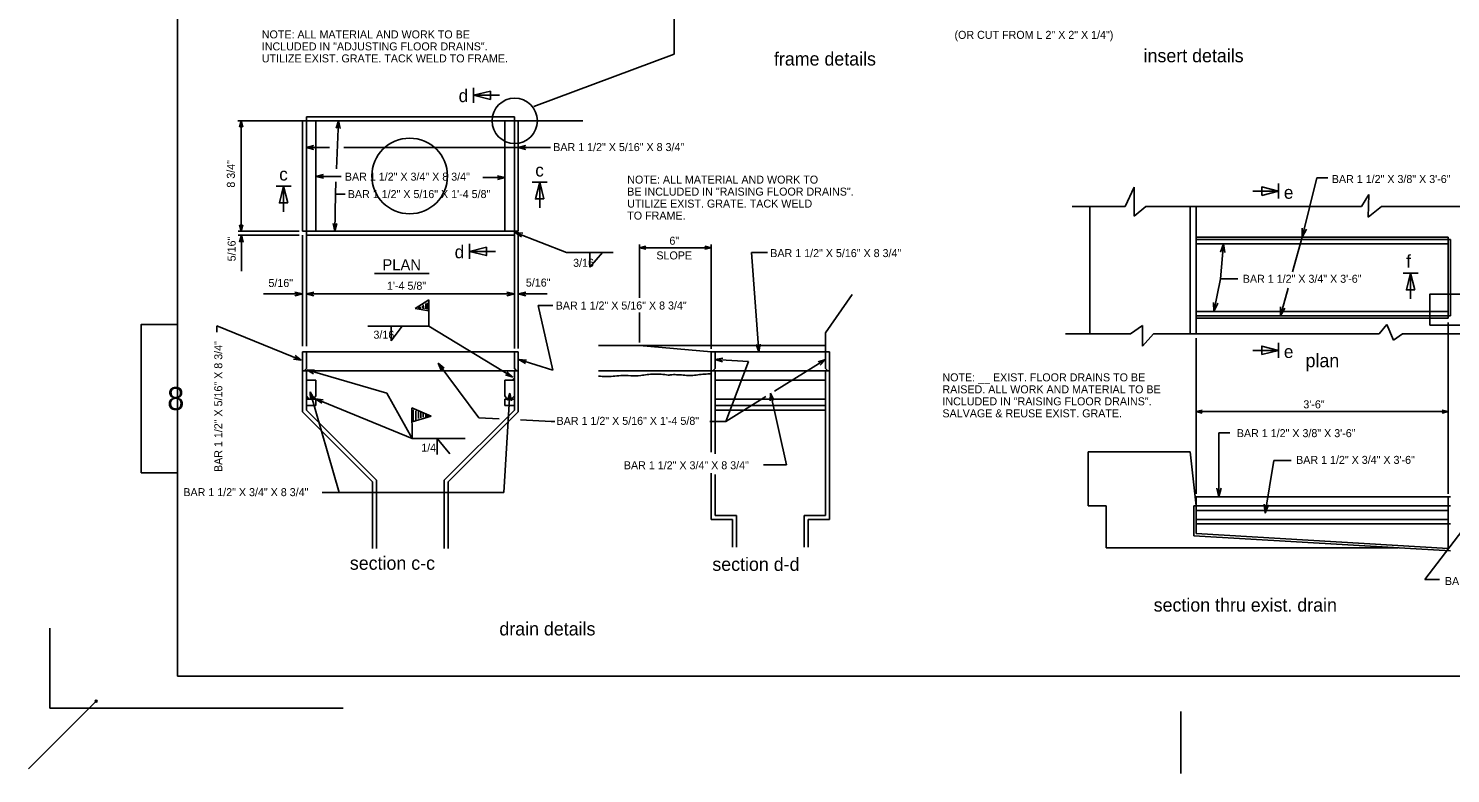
# Model space of a CAD drawing. Extents: x 973.2 to 1069.7, y 1484.4 to 1549.5.
# Drawn here: x 975.6 to 1034.8, y 1484.4 to 1515.4 of the extents above; entities that cross this region are included whole.
import ezdxf

# ---------------------------------------------------------------- set-up
doc = ezdxf.new("R2010")
doc.units = 0
for name, color, linetype in [('Level 1', 7, 'Continuous'), ('Level 2', 7, 'Continuous'), ('Level 37', 7, 'Continuous'), ('Level 49', 7, 'Continuous')]:
    doc.layers.add(name, color=color, linetype=linetype)

msp = doc.modelspace()

# ---------------------------------------------------------------- linework, layer by layer
at = {"layer": 'Level 1'}
for p, q in [((981.8, 1488.431), (981.8, 1544.364)), ((976.473, 1490.436), (976.473, 1487.1)), ((981.8, 1488.431), (1065.368, 1488.431)), ((976.473, 1487.1), (988.692, 1487.1))]:
    msp.add_line(p, q, dxfattribs=at)
msp.add_lwpolyline([(981.799, 1503.093), (980.288, 1503.093), (980.288, 1496.91), (981.799, 1496.91)], close=True, dxfattribs=at)
at = {"layer": 'Level 2'}
for p, q in [((1002.483, 1514.351), (1002.483, 1538.904)), ((996.637, 1512.173), (1002.483, 1514.351)), ((994.121, 1512.954), (994.121, 1512.33)), ((994.121, 1512.642), (995.2, 1512.642)), ((986.999, 1511.575), (984.308, 1511.575)), ((984.448, 1506.982), (984.448, 1511.575)), ((986.999, 1511.575), (995.989, 1511.575)), ((986.999, 1506.982), (986.999, 1511.575)), ((987.163, 1511.739), (995.825, 1511.739)), ((987.163, 1506.818), (987.163, 1511.739)), ((987.557, 1506.982), (987.557, 1511.575)), ((988.497, 1511.575), (988.406, 1511.264)), ((988.417, 1509.579), (988.497, 1511.575)), ((988.497, 1511.575), (988.564, 1511.257)), ((995.432, 1506.982), (995.432, 1511.575)), ((995.825, 1506.818), (995.825, 1511.739)), ((995.989, 1506.982), (995.989, 1511.575)), ((995.989, 1511.575), (998.674, 1511.575)), ((987.163, 1510.464), (987.478, 1510.543)), ((987.163, 1510.464), (987.478, 1510.386)), ((988.129, 1510.464), (987.163, 1510.464)), ((995.989, 1510.464), (988.718, 1510.464)), ((995.989, 1510.464), (996.304, 1510.543)), ((997.335, 1510.464), (995.989, 1510.464)), ((995.989, 1510.464), (996.304, 1510.386)), ((987.557, 1509.262), (987.872, 1509.34)), ((988.615, 1509.262), (987.557, 1509.262)), ((987.557, 1509.262), (987.872, 1509.183)), ((994.518, 1509.212), (995.433, 1509.212)), ((995.433, 1509.212), (995.118, 1509.291)), ((995.433, 1509.212), (995.118, 1509.134)), ((986.528, 1508.86), (985.904, 1508.86)), ((986.216, 1508.86), (986.216, 1507.782)), ((988.375, 1508.525), (988.396, 1509.04)), ((997.193, 1509.027), (996.569, 1509.027)), ((996.881, 1509.027), (996.881, 1507.949)), ((1021.261, 1508.01), (1021.637, 1508.81)), ((1021.637, 1508.81), (1021.637, 1507.607)), ((1027.658, 1508.646), (1026.579, 1508.646)), ((1027.658, 1508.334), (1027.658, 1508.958)), ((1029.25, 1509.194), (1028.642, 1506.729)), ((1029.707, 1509.194), (1029.25, 1509.194)), ((988.375, 1508.525), (988.35, 1506.982)), ((988.781, 1508.525), (988.375, 1508.525)), ((1031.414, 1508.509), (1031.115, 1508.01)), ((1031.414, 1508.509), (1031.389, 1507.556)), ((1019.055, 1508.01), (1021.261, 1508.01)), ((1019.799, 1502.7), (1019.799, 1508.01)), ((1021.637, 1507.607), (1022.121, 1508.01)), ((1022.121, 1508.01), (1031.115, 1508.01)), ((1023.974, 1502.7), (1023.974, 1508.01)), ((1024.223, 1502.7), (1024.223, 1508.01)), ((1031.389, 1507.556), (1031.941, 1508.01)), ((1031.941, 1508.01), (1036.804, 1508.01)), ((986.868, 1506.982), (984.317, 1506.982)), ((986.999, 1506.982), (995.989, 1506.982)), ((988.35, 1506.982), (988.276, 1507.298)), ((988.35, 1506.982), (988.434, 1507.295)), ((997.998, 1506.091), (995.862, 1506.929)), ((995.862, 1506.929), (996.184, 1506.888)), ((995.862, 1506.929), (996.127, 1506.741)), ((1028.642, 1506.729), (1028.641, 1507.1)), ((1028.642, 1506.729), (1028.815, 1507.057)), ((986.868, 1506.818), (984.317, 1506.818)), ((984.454, 1506.832), (984.376, 1506.517)), ((984.454, 1506.832), (984.454, 1505.311)), ((984.454, 1506.832), (984.533, 1506.517)), ((986.999, 1506.818), (986.999, 1502.179)), ((987.163, 1506.818), (995.825, 1506.818)), ((987.163, 1506.818), (987.163, 1502.179)), ((993.957, 1506.444), (993.957, 1505.82)), ((995.825, 1506.818), (995.825, 1502.089)), ((995.989, 1506.818), (995.989, 1502.089)), ((1001.038, 1504.204), (1001.038, 1506.419)), ((1001.038, 1506.288), (1004.024, 1506.288)), ((1004.024, 1502.08), (1004.024, 1506.419)), ((1024.223, 1506.729), (1034.724, 1506.729)), ((1024.223, 1506.635), (1024.223, 1506.729)), ((1024.223, 1506.635), (1034.818, 1506.635)), ((1024.223, 1506.448), (1024.223, 1506.635)), ((1024.223, 1506.448), (1034.724, 1506.448)), ((1025.233, 1504.995), (1025.355, 1506.448)), ((1025.355, 1506.448), (1025.235, 1506.097)), ((1025.355, 1506.448), (1025.415, 1506.082)), ((1028.642, 1506.729), (1028.238, 1505.279)), ((1034.724, 1503.354), (1034.724, 1506.729)), ((1034.818, 1503.448), (1034.818, 1506.635)), ((993.957, 1506.132), (995.036, 1506.132)), ((997.998, 1506.091), (999.937, 1506.091)), ((998.973, 1506.091), (998.973, 1505.475)), ((998.973, 1505.475), (999.496, 1506.091)), ((1006.371, 1506.088), (1005.708, 1506.088)), ((1005.708, 1506.088), (1006.005, 1501.949)), ((989.995, 1505.211), (992.279, 1505.211)), ((1033.466, 1505.231), (1032.842, 1505.231)), ((1033.154, 1505.231), (1033.154, 1504.152)), ((1024.959, 1503.635), (1025.233, 1504.995)), ((1025.964, 1504.995), (1025.233, 1504.995)), ((1028.051, 1504.607), (1027.729, 1503.448)), ((986.999, 1504.36), (985.376, 1504.36)), ((986.999, 1504.36), (986.684, 1504.438)), ((986.999, 1504.36), (986.684, 1504.281)), ((987.163, 1504.36), (987.478, 1504.438)), ((987.163, 1504.36), (995.825, 1504.36)), ((987.163, 1504.36), (987.478, 1504.281)), ((992.258, 1504.11), (991.691, 1503.76)), ((992.06, 1503.741), (992.032, 1503.902)), ((992.136, 1503.741), (992.136, 1503.968)), ((992.202, 1503.713), (992.202, 1503.987)), ((992.258, 1503.023), (992.258, 1504.11)), ((995.825, 1504.36), (995.51, 1504.438)), ((995.825, 1504.36), (995.51, 1504.281)), ((995.989, 1504.36), (996.304, 1504.438)), ((995.989, 1504.36), (997.197, 1504.36)), ((995.989, 1504.36), (996.304, 1504.281)), ((997.434, 1503.885), (996.82, 1503.885)), ((996.82, 1503.885), (997.434, 1501.184)), ((1008.782, 1502.736), (1009.9, 1504.334)), ((1024.959, 1503.635), (1024.942, 1504.006)), ((1024.959, 1503.635), (1025.119, 1503.971)), ((991.691, 1503.76), (992.258, 1503.656)), ((991.862, 1503.76), (991.833, 1503.817)), ((991.909, 1503.76), (991.909, 1503.826)), ((991.994, 1503.76), (991.994, 1503.855)), ((1001.038, 1502.342), (1001.038, 1503.591)), ((1024.223, 1503.635), (1034.724, 1503.635)), ((1024.223, 1503.635), (1024.223, 1503.448)), ((1024.223, 1503.448), (1034.818, 1503.448)), ((1024.223, 1503.354), (1024.223, 1503.448)), ((1024.223, 1503.354), (1034.724, 1503.354)), ((1027.729, 1503.448), (1027.739, 1503.819)), ((1027.729, 1503.448), (1027.912, 1503.771)), ((983.44, 1502.774), (983.44, 1503.027)), ((983.44, 1503.027), (986.951, 1501.602)), ((992.258, 1503.023), (989.725, 1503.023)), ((990.689, 1503.023), (990.689, 1502.406)), ((990.689, 1502.406), (991.153, 1503.023)), ((992.258, 1503.023), (995.76, 1500.89)), ((1008.782, 1502.211), (1008.782, 1502.736)), ((1018.779, 1502.7), (1021.487, 1502.7)), ((1021.487, 1502.7), (1021.988, 1503.044)), ((1021.988, 1503.044), (1021.988, 1502.191)), ((1021.988, 1502.191), (1022.449, 1502.7)), ((1022.449, 1502.7), (1031.841, 1502.7)), ((1031.841, 1502.7), (1032.167, 1503.094)), ((1032.167, 1503.094), (1032.442, 1502.442)), ((1032.442, 1502.442), (1032.818, 1502.7)), ((1032.818, 1502.7), (1036.83, 1502.7)), ((1034.724, 1499.584), (1034.724, 1503.169)), ((999.334, 1502.211), (1008.782, 1502.211)), ((1001.038, 1502.211), (1004.024, 1501.949)), ((1006.005, 1501.949), (1005.903, 1502.257)), ((1006.005, 1501.949), (1006.06, 1502.268)), ((1008.782, 1501.949), (1008.782, 1502.211)), ((1024.224, 1499.584), (1024.224, 1502.517)), ((1027.658, 1501.698), (1027.658, 1502.322)), ((986.951, 1501.602), (986.629, 1501.647)), ((986.951, 1501.602), (986.689, 1501.793)), ((986.999, 1501.161), (986.999, 1501.948)), ((986.999, 1501.948), (987.163, 1501.948)), ((987.163, 1501.948), (995.825, 1501.948)), ((987.163, 1501.948), (987.163, 1501.255)), ((995.989, 1501.948), (995.825, 1501.948)), ((995.825, 1501.948), (995.825, 1501.255)), ((995.989, 1501.161), (995.989, 1501.948)), ((997.434, 1501.184), (996.01, 1501.627)), ((996.01, 1501.627), (996.334, 1501.608)), ((996.01, 1501.627), (996.287, 1501.458)), ((1004.024, 1501.161), (1004.024, 1501.949)), ((1004.024, 1501.949), (1004.187, 1501.949)), ((1004.188, 1501.949), (1008.781, 1501.949)), ((1004.188, 1501.949), (1004.188, 1501.255)), ((1004.188, 1501.627), (1004.506, 1501.688)), ((1005.584, 1501.553), (1004.188, 1501.627)), ((1004.188, 1501.627), (1004.498, 1501.531)), ((1004.635, 1499.049), (1005.584, 1501.553)), ((1006.655, 1500.304), (1008.781, 1501.627)), ((1008.781, 1501.627), (1008.473, 1501.527)), ((1008.781, 1501.627), (1008.556, 1501.393)), ((1008.781, 1501.949), (1008.781, 1501.255)), ((1008.945, 1501.949), (1008.782, 1501.949)), ((1008.945, 1501.161), (1008.945, 1501.949)), ((1027.658, 1502.01), (1026.579, 1502.01)), ((986.999, 1501.161), (995.989, 1501.161)), ((986.999, 1501.161), (986.999, 1499.455)), ((987.069, 1501.161), (986.999, 1501.161)), ((987.163, 1501.255), (987.069, 1501.161)), ((987.087, 1501.161), (987.163, 1501.161)), ((987.163, 1501.161), (987.163, 1499.523)), ((990.508, 1500.225), (987.178, 1501.195)), ((987.178, 1501.195), (987.502, 1501.182)), ((987.178, 1501.195), (987.458, 1501.031)), ((992.646, 1501.479), (994.34, 1499.196)), ((992.646, 1501.479), (992.897, 1501.273)), ((992.646, 1501.479), (992.771, 1501.18)), ((995.76, 1500.89), (995.45, 1500.987)), ((995.76, 1500.89), (995.532, 1501.121)), ((995.825, 1501.255), (995.919, 1501.161)), ((995.825, 1501.161), (995.825, 1499.523)), ((995.919, 1501.161), (995.989, 1501.161)), ((995.989, 1501.161), (995.989, 1499.455)), ((999.334, 1501.161), (1008.946, 1501.161)), ((1004.093, 1501.161), (1004.024, 1501.161)), ((1004.024, 1501.161), (1004.024, 1497.772)), ((1004.188, 1501.255), (1004.093, 1501.161)), ((1004.188, 1501.161), (1008.781, 1501.161)), ((1004.188, 1501.161), (1004.188, 1497.698)), ((1008.781, 1501.255), (1008.876, 1501.161)), ((1008.782, 1501.161), (1008.782, 1495.124)), ((1008.876, 1501.161), (1008.945, 1501.161)), ((1008.946, 1501.161), (1008.946, 1494.96)), ((987.557, 1500.768), (987.163, 1500.768)), ((987.163, 1500.768), (987.163, 1500.103)), ((987.557, 1500.113), (987.557, 1500.768)), ((995.432, 1500.112), (995.432, 1500.768)), ((995.432, 1500.768), (995.825, 1500.768)), ((995.732, 1500.768), (995.826, 1500.862)), ((995.826, 1500.768), (995.826, 1500.112)), ((1004.188, 1500.768), (1008.782, 1500.768)), ((1004.188, 1499.98), (1004.188, 1500.768)), ((1008.782, 1499.98), (1008.782, 1500.768)), ((987.163, 1500.103), (987.27, 1499.98)), ((987.163, 1499.98), (987.557, 1499.98)), ((987.27, 1499.98), (987.463, 1499.98)), ((988.53, 1496.085), (987.319, 1500.276)), ((987.319, 1500.276), (987.482, 1499.995)), ((987.319, 1500.276), (987.331, 1499.952)), ((987.463, 1499.98), (987.557, 1500.113)), ((991.57, 1498.336), (987.539, 1499.996)), ((987.539, 1499.996), (987.86, 1499.949)), ((987.539, 1499.996), (987.8, 1499.804)), ((987.557, 1499.98), (987.557, 1499.718)), ((991.57, 1498.336), (990.508, 1500.225)), ((995.393, 1496.085), (995.642, 1500.227)), ((995.432, 1500.112), (995.527, 1499.98)), ((995.432, 1499.98), (995.432, 1499.718)), ((995.432, 1499.98), (995.825, 1499.98)), ((995.695, 1499.98), (995.527, 1499.98)), ((995.642, 1500.227), (995.544, 1499.917)), ((995.642, 1500.227), (995.701, 1499.908)), ((995.695, 1499.98), (995.826, 1500.112)), ((1004.188, 1499.98), (1008.782, 1499.98)), ((1004.635, 1499.049), (1006.304, 1500.086)), ((1006.493, 1500.225), (1006.484, 1499.901)), ((1007.153, 1497.245), (1006.493, 1500.225)), ((1006.493, 1500.225), (1006.638, 1499.934)), ((986.999, 1499.455), (989.92, 1496.535)), ((987.163, 1499.718), (987.557, 1499.718)), ((987.163, 1499.523), (990.083, 1496.602)), ((991.56, 1499.613), (991.57, 1498.336)), ((991.56, 1499.613), (992.364, 1499.272)), ((992.364, 1499.272), (991.564, 1499.036)), ((991.612, 1499.074), (991.612, 1499.532)), ((991.726, 1499.121), (991.726, 1499.485)), ((991.839, 1499.173), (991.839, 1499.461)), ((991.924, 1499.192), (991.924, 1499.419)), ((992.028, 1499.22), (992.028, 1499.376)), ((992.141, 1499.234), (992.141, 1499.358)), ((992.212, 1499.258), (992.212, 1499.301)), ((995.825, 1499.523), (992.906, 1496.603)), ((995.989, 1499.455), (993.069, 1496.535)), ((994.34, 1499.196), (995.199, 1499.154)), ((995.432, 1499.718), (995.825, 1499.718)), ((1004.188, 1499.718), (1008.782, 1499.718)), ((1004.188, 1499.523), (1008.782, 1499.523)), ((1024.224, 1496.029), (1024.224, 1499.584)), ((1024.224, 1499.459), (1034.724, 1499.459)), ((1034.224, 1499.459), (1034.724, 1499.459)), ((1034.724, 1496.029), (1034.724, 1499.584)), ((1034.724, 1496.751), (1034.724, 1499.584)), ((996.08, 1499.111), (997.36, 1499.049)), ((997.36, 1499.049), (997.513, 1499.049)), ((1003.965, 1499.049), (1004.635, 1499.049)), ((1025.629, 1498.573), (1025.169, 1498.573)), ((1025.169, 1498.573), (1025.172, 1495.904)), ((991.57, 1498.336), (993.772, 1498.336)), ((992.609, 1498.336), (992.609, 1497.675)), ((992.609, 1498.336), (993.134, 1497.703)), ((1023.974, 1497.779), (1019.724, 1497.779)), ((1019.724, 1497.779), (1019.724, 1495.529)), ((1024.224, 1495.529), (1023.974, 1497.779)), ((1027.455, 1497.417), (1027.09, 1495.225)), ((1028.185, 1497.417), (1027.455, 1497.417)), ((1004.024, 1496.888), (1004.024, 1494.96)), ((1004.188, 1496.839), (1004.188, 1495.124)), ((1006.2, 1497.245), (1007.153, 1497.245)), ((989.92, 1496.535), (989.92, 1493.747)), ((990.083, 1496.602), (990.083, 1493.747)), ((992.906, 1496.603), (992.906, 1493.747)), ((993.069, 1496.535), (993.069, 1493.747)), ((1025.172, 1495.904), (1025.082, 1496.264)), ((1025.172, 1495.904), (1025.262, 1496.264)), ((987.825, 1496.085), (995.393, 1496.085)), ((1024.224, 1495.904), (1034.818, 1495.904)), ((1024.224, 1495.529), (1024.224, 1495.904)), ((1027.09, 1495.225), (1027.06, 1495.595)), ((1034.724, 1495.529), (1034.724, 1495.904)), ((1004.188, 1495.124), (1005.074, 1495.124)), ((1005.074, 1495.124), (1005.074, 1493.811)), ((1007.896, 1495.124), (1007.896, 1493.811)), ((1007.896, 1495.124), (1008.782, 1495.124)), ((1019.724, 1495.529), (1020.474, 1495.529)), ((1020.474, 1495.529), (1020.474, 1493.779)), ((1024.13, 1495.529), (1024.13, 1494.284)), ((1024.13, 1495.529), (1024.223, 1495.529)), ((1024.224, 1495.529), (1024.224, 1494.373)), ((1024.224, 1495.529), (1034.818, 1495.529)), ((1024.224, 1495.341), (1034.724, 1495.341)), ((1024.224, 1494.966), (1024.224, 1495.341)), ((1027.09, 1495.225), (1027.238, 1495.566)), ((1034.724, 1495.529), (1034.724, 1493.754)), ((1034.724, 1494.966), (1034.724, 1495.341)), ((1004.024, 1494.96), (1004.91, 1494.96)), ((1004.91, 1494.96), (1004.91, 1493.811)), ((1008.06, 1494.96), (1008.06, 1493.811)), ((1008.06, 1494.96), (1008.946, 1494.96)), ((1024.224, 1494.966), (1034.724, 1494.966)), ((1024.224, 1494.779), (1034.818, 1494.779)), ((1033.748, 1492.456), (1035.642, 1494.951)), ((1024.13, 1494.284), (1034.818, 1493.654)), ((1024.224, 1494.373), (1034.724, 1493.754)), ((1020.474, 1493.779), (1032.634, 1493.779)), ((1034.363, 1492.456), (1033.748, 1492.456)), ((975.587, 1484.565), (978.412, 1487.39))]:
    msp.add_line(p, q, dxfattribs=at)
for points in [[(994.825, 1512.818), (994.121, 1512.642), (994.825, 1512.466)], [(986.391, 1508.157), (986.216, 1508.86), (986.04, 1508.157)], [(997.057, 1508.324), (996.881, 1509.027), (996.705, 1508.324)], [(1026.955, 1508.47), (1027.658, 1508.646), (1026.955, 1508.822)], [(994.661, 1506.308), (993.957, 1506.132), (994.661, 1505.957)], [(1033.33, 1504.527), (1033.154, 1505.231), (1032.978, 1504.527)], [(1033.951, 1503.057), (1033.951, 1504.346), (1035.311, 1504.346), (1035.311, 1503.057)], [(1026.955, 1501.834), (1027.658, 1502.01), (1026.955, 1502.186)]]:
    msp.add_lwpolyline(points, close=True, dxfattribs=at)
for points in [[(984.382, 1511.313), (984.448, 1511.575), (984.514, 1511.313)], [(984.382, 1507.244), (984.448, 1506.982), (984.514, 1507.244)], [(1001.3, 1506.353), (1001.038, 1506.288), (1001.3, 1506.222)], [(1003.761, 1506.353), (1004.024, 1506.288), (1003.761, 1506.222)], [(1024.474, 1499.522), (1024.224, 1499.459), (1024.474, 1499.397)], [(1034.474, 1499.522), (1034.724, 1499.459), (1034.474, 1499.397)], [(1034.474, 1499.522), (1034.724, 1499.459), (1034.474, 1499.397)]]:
    msp.add_lwpolyline(points, dxfattribs=at)
for centre, radius in [((995.839, 1511.576), 0.944), ((991.464, 1509.278), 1.575)]:
    msp.add_circle(centre, radius, dxfattribs=at)
for points in [[(1002.233, 1500.976), (1001.942, 1501.016), (1001.635, 1501.016), (1001.356, 1501.002), (1001.091, 1500.96), (1000.255, 1500.96), (999.934, 1500.932), (999.334, 1500.932)], [(1004.024, 1501.032), (1003.745, 1501.019), (1003.471, 1500.994), (1003.191, 1500.957), (1002.924, 1500.976), (1002.65, 1500.994), (1002.383, 1500.994), (1002.233, 1500.976)]]:
    msp.add_spline(points, degree=3, dxfattribs=at)
at = {"layer": 'Level 37'}
msp.add_line((1023.584, 1486.962), (1023.584, 1484.372), dxfattribs=at)
at = {"layer": 'Level 49'}
msp.add_circle((978.412, 1487.39), 0.0404, dxfattribs=at)

# ---------------------------------------------------------------- texts
at = {"layer": 'Level 1'}
msp.add_text('8', height=0.962, dxfattribs=at).set_placement((981.366, 1499.521))
at = {"layer": 'Level 2'}
for s, height, p in [('NOTE: ALL MATERIAL AND WORK TO BE ', 0.33333, (985.306, 1515.012)), ('(OR CUT FROM L 2" X 2" X 1/4")', 0.33333, (1014.157, 1514.993)), ('INCLUDED IN "ADJUSTING FLOOR DRAINS".', 0.33333, (985.306, 1514.512)), ('insert details', 0.555, (1022.033, 1514.017)), ('UTILIZE EXIST. GRATE. TACK WELD TO FRAME.', 0.33333, (985.306, 1514.012)), ('frame details', 0.555, (1006.637, 1513.882)), ('BAR 1 1/2" X 5/16" X 8 3/4"', 0.33333, (997.444, 1510.316)), ('BAR 1 1/2" X 3/4" X 8 3/4"', 0.33333, (988.766, 1509.083)), ('NOTE: ALL MATERIAL AND WORK TO', 0.33333, (1000.527, 1508.96)), ('BAR 1 1/2" X 3/8" X 3\'-6"', 0.33333, (1029.871, 1508.984)), ('BAR 1 1/2" X 5/16" X 1\'-4 5/8"', 0.33333, (988.887, 1508.357)), ('BE INCLUDED IN "RAISING FLOOR DRAINS".', 0.33333, (1000.527, 1508.46)), ('e ', 0.5333, (1027.875, 1508.328)), ('UTILIZE EXIST. GRATE. TACK WELD', 0.33333, (1000.527, 1507.96)), ('TO FRAME.', 0.3333, (1000.527, 1507.46)), ('6"', 0.3333, (1002.283, 1506.413)), ('BAR 1 1/2" X 5/16" X 8 3/4"', 0.33333, (1006.484, 1505.897)), ('PLAN', 0.4594, (990.331, 1505.349)), ('3/16', 0.3333, (998.272, 1505.492)), ('SLOPE', 0.3333, (1001.741, 1505.8)), ('BAR 1 1/2" X 3/4" X 3\'-6"', 0.33333, (1026.164, 1504.827)), ('5/16"', 0.3333, (985.583, 1504.652)), ('1\'-4 5/8"', 0.3333, (990.52, 1504.536)), ('5/16"', 0.3333, (996.304, 1504.669)), ('BAR 1 1/2" X 5/16" X 8 3/4"', 0.33333, (997.547, 1503.713)), ('3/16', 0.3333, (989.956, 1502.497)), ('e ', 0.5333, (1027.875, 1501.692)), ('plan', 0.555, (1028.779, 1501.309)), ('NOTE: __ EXIST. FLOOR DRAINS TO BE ', 0.33333, (1013.654, 1500.719)), ('RAISED. ALL WORK AND MATERIAL TO BE', 0.33333, (1013.654, 1500.219)), ('INCLUDED IN "RAISING FLOOR DRAINS".', 0.33333, (1013.654, 1499.719)), ('3\'-6"', 0.3333, (1028.686, 1499.594)), ('BAR 1 1/2" X 5/16" X 1\'-4 5/8"', 0.33333, (997.583, 1498.906)), ('SALVAGE & REUSE EXIST. GRATE.', 0.33333, (1013.654, 1499.219)), ('BAR 1 1/2" X 3/8" X 3\'-6"', 0.33333, (1025.915, 1498.393)), ('1/4', 0.3333, (991.947, 1497.787)), ('BAR 1 1/2" X 3/4" X 8 3/4"', 0.33333, (1000.386, 1497.054)), ('BAR 1 1/2" X 3/4" X 3\'-6"', 0.33333, (1028.385, 1497.279)), ('BAR 1 1/2" X 3/4" X 8 3/4"', 0.33333, (982.039, 1495.934)), ('section c-c', 0.555, (988.973, 1492.866)), ('section d-d', 0.555, (1004.071, 1492.82)), ('BAR 1 1/2" X 3/8" X 1\'-0 3/4"', 0.33333, (1034.582, 1492.23)), ('section thru exist. drain', 0.555, (1022.454, 1491.123)), ('drain details', 0.555, (995.201, 1490.129))]:
    msp.add_text(s, height=height, dxfattribs=at).set_placement(p)
for s, height, rotation, p in [('d ', 0.5333, 360, (993.504, 1512.358)), ('8 3/4"', 0.3333, 90, (984.184, 1508.792)), ('c ', 0.5333, 360, (986.032, 1509.088)), ('c ', 0.5333, 360, (996.697, 1509.255)), ('5/16"', 0.3333, 90, (984.216, 1505.722)), ('d ', 0.5333, 360, (993.339, 1505.848)), ('f ', 0.5333, 360, (1032.97, 1505.458)), ('BAR 1 1/2" X 5/16" X 8 3/4"', 0.33333, 90, (983.661, 1496.94))]:
    msp.add_text(s, height=height, rotation=rotation, dxfattribs=at).set_placement(p)

doc.saveas('drawing.dxf')
